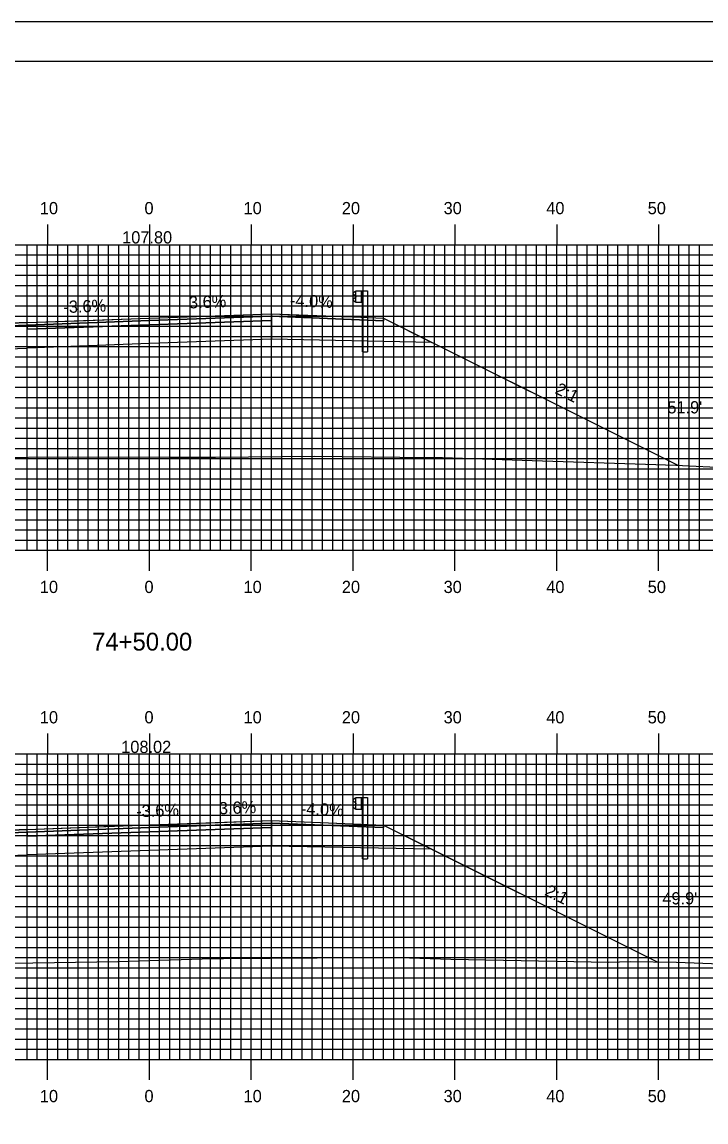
# Model space of a CAD drawing. Extents: x 1761004 to 1761347, y 442591 to 442811.
# Drawn here: x 1761157.2 to 1761224.4, y 442702.5 to 442810.5 of the extents above; entities that cross this region are included whole.
import ezdxf

# ---------------------------------------------------------------- set-up
doc = ezdxf.new("R2010")
doc.units = 0
for name, color, linetype in [('ANNOTATION', 7, 'Continuous'), ('BORDER', 7, 'Continuous'), ('D_Guardrail_Beam_Rt', 7, 'Continuous'), ('D_Roadway_Centerline', 7, 'Continuous'), ('D_Roadway_Centerline_Text', 7, 'Continuous'), ('D_Roadway_Edge_Shoulder', 7, 'Continuous'), ('D_Roadway_Edge_TW', 7, 'Continuous'), ('D_Roadway_Pavement', 7, 'Continuous'), ('D_Roadway_SlopeLines', 7, 'Continuous'), ('D_Roadway_SubGrade', 7, 'Continuous'), ('D_Text_Standard', 7, 'Continuous'), ('H_V ANNOTATION', 7, 'Continuous'), ('MAJOR', 7, 'Continuous'), ('MINOR', 7, 'Continuous'), ('PLOT BOUNDARY', 7, 'Continuous'), ('S_Roadway_Centerline', 7, 'Continuous')]:
    doc.layers.add(name, color=color, linetype=linetype)

msp = doc.modelspace()

# ---------------------------------------------------------------- linework, layer by layer
at = {"layer": 'BORDER'}
msp.add_lwpolyline([(1761020.13, 442596.67), (1761340.13, 442596.67), (1761340.13, 442806.67), (1761020.13, 442806.67)], close=True, dxfattribs=at)
at = {"layer": 'D_Guardrail_Beam_Rt'}
for p, q in [((1761189.91, 442784.06), (1761189.76, 442783.96)), ((1761189.76, 442783.81), (1761189.96, 442783.68)), ((1761190, 442784.08), (1761189.92, 442784.06)), ((1761189.99, 442783.61), (1761189.99, 442783.54)), ((1761190, 442784.16), (1761190.69, 442784.16)), ((1761190, 442782.99), (1761190, 442784.16)), ((1761190.52, 442784.16), (1761190.52, 442782.99)), ((1761190.62, 442784.16), (1761190.62, 442782.99)), ((1761190.69, 442784.16), (1761191.16, 442784.16)), ((1761190.69, 442784.16), (1761190.69, 442782.99)), ((1761191.16, 442784.16), (1761191.16, 442778.16)), ((1761189.96, 442783.48), (1761189.76, 442783.34)), ((1761189.76, 442783.2), (1761189.91, 442783.1)), ((1761189.92, 442783.09), (1761190, 442783.08)), ((1761190.69, 442782.99), (1761190, 442782.99)), ((1761190.66, 442778.16), (1761190.66, 442782.99)), ((1761190.66, 442778.16), (1761191.16, 442778.16)), ((1761189.91, 442734.28), (1761189.76, 442734.18)), ((1761189.76, 442734.03), (1761189.96, 442733.9)), ((1761190, 442734.3), (1761189.92, 442734.28)), ((1761190, 442734.38), (1761190.69, 442734.38)), ((1761190, 442733.21), (1761190, 442734.38)), ((1761190.52, 442734.38), (1761190.52, 442733.21)), ((1761190.62, 442734.38), (1761190.62, 442733.21)), ((1761190.69, 442734.38), (1761191.16, 442734.38)), ((1761190.69, 442734.38), (1761190.69, 442733.21)), ((1761191.16, 442734.38), (1761191.16, 442728.38)), ((1761189.96, 442733.7), (1761189.76, 442733.56)), ((1761189.76, 442733.42), (1761189.91, 442733.32)), ((1761189.92, 442733.31), (1761190, 442733.3)), ((1761189.99, 442733.83), (1761189.99, 442733.76)), ((1761190.69, 442733.21), (1761190, 442733.21)), ((1761190.66, 442728.38), (1761190.66, 442733.21)), ((1761190.66, 442728.38), (1761191.16, 442728.38))]:
    msp.add_line(p, q, dxfattribs=at)
for centre, major_axis, start_param, end_param in [((1761189.81, 442783.88), (-0.0877, 0), 5.323254, 7.243116), ((1761189.93, 442784.02), (-0.0417, 0), 4.907132, 5.323254), ((1761189.91, 442783.61), (0.0789, 0), 0, 0.959931), ((1761189.81, 442783.27), (-0.0877, 0), 5.323254, 7.243116), ((1761189.93, 442783.13), (-0.0417, 0), 0.959931, 1.376053), ((1761189.91, 442783.54), (0.0789, 0), 5.323254, 6.283185), ((1761189.81, 442734.1), (-0.0877, 0), 5.323254, 7.243116), ((1761189.93, 442734.24), (-0.0417, 0), 4.907132, 5.323254), ((1761189.81, 442733.49), (-0.0877, 0), 5.323254, 7.243116), ((1761189.93, 442733.35), (-0.0417, 0), 0.959931, 1.376053), ((1761189.91, 442733.83), (0.0789, 0), 0, 0.959931), ((1761189.91, 442733.76), (0.0789, 0), 5.323254, 6.283185)]:
    msp.add_ellipse(centre, major_axis=major_axis, ratio=0.995501, start_param=start_param, end_param=end_param, dxfattribs=at)
at = {"layer": 'D_Roadway_Centerline'}
for points in [[(1761153.4, 442780.86), (1761157.73, 442781.03), (1761162.64, 442781.21), (1761169.72, 442781.46), (1761169.73, 442781.47), (1761169.73, 442781.47), (1761172.49, 442781.56), (1761181.73, 442781.9), (1761187.35, 442781.67), (1761189.73, 442781.58), (1761189.73, 442781.58), (1761192.73, 442781.46), (1761192.73, 442781.45), (1761194.56, 442780.54), (1761197.48, 442779.08), (1761197.49, 442779.08), (1761212.78, 442771.43), (1761221.61, 442767.02), (1761221.63, 442767.01)], [(1761120.16, 442717.53), (1761133.13, 442724.02), (1761141.43, 442728.17), (1761146.73, 442730.81), (1761146.74, 442730.81), (1761149.72, 442730.93), (1761149.73, 442730.93), (1761157.72, 442731.25), (1761157.73, 442731.25), (1761166.12, 442731.56), (1761169.73, 442731.69), (1761175.62, 442731.9), (1761181.72, 442732.12), (1761181.73, 442732.12), (1761181.73, 442732.12), (1761185.69, 442731.96), (1761189.73, 442731.8), (1761192.73, 442731.68), (1761196.28, 442729.9), (1761197.48, 442729.3), (1761197.48, 442729.3), (1761202.44, 442726.82), (1761219.6, 442718.24)]]:
    msp.add_lwpolyline(points, dxfattribs=at)
at = {"layer": 'D_Roadway_Edge_Shoulder'}
for points in [[(1761181.73, 442781.9), (1761189.73, 442781.58), (1761189.73, 442781.58), (1761192.73, 442781.46), (1761192.73, 442781.21), (1761181.73, 442781.65)], [(1761157.73, 442781.03), (1761149.73, 442780.71), (1761149.73, 442780.71), (1761146.73, 442780.59), (1761146.73, 442780.34), (1761157.73, 442780.78)], [(1761181.73, 442732.12), (1761189.73, 442731.8), (1761189.73, 442731.8), (1761192.73, 442731.68), (1761192.73, 442731.43), (1761181.73, 442731.87)], [(1761157.73, 442731.25), (1761149.73, 442730.93), (1761149.73, 442730.93), (1761146.73, 442730.81), (1761146.73, 442730.56), (1761157.73, 442731)]]:
    msp.add_lwpolyline(points, close=True, dxfattribs=at)
at = {"layer": 'D_Roadway_Edge_TW'}
for points in [[(1761157.73, 442780.78), (1761157.73, 442781.03), (1761169.73, 442781.47), (1761181.73, 442781.9), (1761181.73, 442781.65), (1761169.73, 442781.22)], [(1761157.73, 442731), (1761157.73, 442731.25), (1761169.73, 442731.69), (1761181.73, 442732.12), (1761181.73, 442731.87), (1761169.73, 442731.44)]]:
    msp.add_lwpolyline(points, close=True, dxfattribs=at)
at = {"layer": 'D_Roadway_Pavement'}
for points in [[(1761157.73, 442780.37), (1761157.73, 442780.78), (1761169.73, 442781.22), (1761181.73, 442781.65), (1761181.73, 442781.23), (1761169.73, 442780.8)], [(1761157.73, 442730.59), (1761157.73, 442731), (1761169.73, 442731.44), (1761181.73, 442731.87), (1761181.73, 442731.45), (1761169.73, 442731.02)]]:
    msp.add_lwpolyline(points, close=True, dxfattribs=at)
for points in [[(1761181.73, 442781.65), (1761181.73, 442781.23)], [(1761157.73, 442780.78), (1761157.73, 442780.37)], [(1761181.73, 442731.87), (1761181.73, 442731.45)], [(1761157.73, 442731), (1761157.73, 442730.59)]]:
    msp.add_lwpolyline(points, dxfattribs=at)
at = {"layer": 'D_Roadway_SlopeLines'}
for points in [[(1761192.73, 442781.46), (1761221.63, 442767.01)], [(1761192.73, 442731.68), (1761219.6, 442718.24)]]:
    msp.add_lwpolyline(points, dxfattribs=at)
at = {"layer": 'D_Roadway_SubGrade'}
for points in [[(1761157.73, 442778.53), (1761157.73, 442780.78), (1761157.73, 442780.37), (1761169.73, 442780.8), (1761181.73, 442781.23), (1761181.73, 442781.65), (1761181.73, 442779.4), (1761169.73, 442778.97)], [(1761181.73, 442781.23), (1761181.73, 442781.65), (1761192.73, 442781.21), (1761192.73, 442781.46), (1761197.48, 442779.08), (1761181.73, 442779.4)], [(1761157.73, 442780.37), (1761157.73, 442780.78), (1761146.73, 442780.34), (1761146.73, 442780.59), (1761141.43, 442777.95), (1761157.73, 442778.53)], [(1761157.73, 442728.75), (1761157.73, 442731), (1761157.73, 442730.59), (1761169.73, 442731.02), (1761181.73, 442731.45), (1761181.73, 442731.87), (1761181.73, 442729.62), (1761169.73, 442729.19)], [(1761181.73, 442731.45), (1761181.73, 442731.87), (1761192.73, 442731.43), (1761192.73, 442731.68), (1761197.48, 442729.3), (1761181.73, 442729.62)], [(1761157.73, 442730.59), (1761157.73, 442731), (1761146.73, 442730.56), (1761146.73, 442730.81), (1761141.43, 442728.17), (1761157.73, 442728.75)]]:
    msp.add_lwpolyline(points, close=True, dxfattribs=at)
at = {"layer": 'MAJOR'}
for p, q in [((1761159.73, 442790.67), (1761159.73, 442788.67)), ((1761169.73, 442790.67), (1761169.73, 442788.67)), ((1761179.73, 442790.67), (1761179.73, 442788.67)), ((1761189.73, 442790.67), (1761189.73, 442788.67)), ((1761199.73, 442790.67), (1761199.73, 442788.67)), ((1761209.73, 442790.67), (1761209.73, 442788.67)), ((1761219.73, 442790.67), (1761219.73, 442788.67)), ((1761029.73, 442788.67), (1761309.73, 442788.67)), ((1761029.73, 442788.67), (1761309.73, 442788.67)), ((1761159.73, 442758.67), (1761159.73, 442788.67)), ((1761169.73, 442758.67), (1761169.73, 442788.67)), ((1761179.73, 442758.67), (1761179.73, 442788.67)), ((1761189.73, 442758.67), (1761189.73, 442788.67)), ((1761199.73, 442758.67), (1761199.73, 442788.67)), ((1761209.73, 442758.67), (1761209.73, 442788.67)), ((1761219.73, 442758.67), (1761219.73, 442788.67)), ((1761029.73, 442783.67), (1761309.73, 442783.67)), ((1761029.73, 442778.67), (1761309.73, 442778.67)), ((1761029.73, 442773.67), (1761309.73, 442773.67)), ((1761029.73, 442768.67), (1761309.73, 442768.67)), ((1761029.73, 442763.67), (1761309.73, 442763.67)), ((1761029.73, 442758.67), (1761309.73, 442758.67)), ((1761029.73, 442758.67), (1761309.73, 442758.67)), ((1761159.73, 442756.66), (1761159.73, 442758.67)), ((1761169.73, 442756.66), (1761169.73, 442758.67)), ((1761179.73, 442756.66), (1761179.73, 442758.67)), ((1761189.73, 442756.66), (1761189.73, 442758.67)), ((1761199.73, 442756.66), (1761199.73, 442758.67)), ((1761209.73, 442756.66), (1761209.73, 442758.67)), ((1761219.73, 442756.66), (1761219.73, 442758.67)), ((1761159.73, 442740.67), (1761159.73, 442738.67)), ((1761169.73, 442740.67), (1761169.73, 442738.67)), ((1761179.73, 442740.67), (1761179.73, 442738.67)), ((1761189.73, 442740.67), (1761189.73, 442738.67)), ((1761199.73, 442740.67), (1761199.73, 442738.67)), ((1761209.73, 442740.67), (1761209.73, 442738.67)), ((1761219.73, 442740.67), (1761219.73, 442738.67)), ((1761029.73, 442738.67), (1761309.73, 442738.67)), ((1761029.73, 442738.67), (1761309.73, 442738.67)), ((1761159.73, 442708.67), (1761159.73, 442738.67)), ((1761169.73, 442708.67), (1761169.73, 442738.67)), ((1761179.73, 442708.67), (1761179.73, 442738.67)), ((1761189.73, 442708.67), (1761189.73, 442738.67)), ((1761199.73, 442708.67), (1761199.73, 442738.67)), ((1761209.73, 442708.67), (1761209.73, 442738.67)), ((1761219.73, 442708.67), (1761219.73, 442738.67)), ((1761029.73, 442733.67), (1761309.73, 442733.67)), ((1761029.73, 442728.67), (1761309.73, 442728.67)), ((1761029.73, 442723.67), (1761309.73, 442723.67)), ((1761029.73, 442718.67), (1761309.73, 442718.67)), ((1761029.73, 442713.67), (1761309.73, 442713.67)), ((1761029.73, 442708.67), (1761309.73, 442708.67)), ((1761029.73, 442708.67), (1761309.73, 442708.67)), ((1761159.73, 442706.66), (1761159.73, 442708.67)), ((1761169.73, 442706.66), (1761169.73, 442708.67)), ((1761179.73, 442706.66), (1761179.73, 442708.67)), ((1761189.73, 442706.66), (1761189.73, 442708.67)), ((1761199.73, 442706.66), (1761199.73, 442708.67)), ((1761209.73, 442706.66), (1761209.73, 442708.67)), ((1761219.73, 442706.66), (1761219.73, 442708.67))]:
    msp.add_line(p, q, dxfattribs=at)
at = {"layer": 'MINOR'}
for p, q in [((1761157.73, 442758.67), (1761157.73, 442788.67)), ((1761158.73, 442758.67), (1761158.73, 442788.67)), ((1761160.73, 442758.67), (1761160.73, 442788.67)), ((1761161.73, 442758.67), (1761161.73, 442788.67)), ((1761162.73, 442758.67), (1761162.73, 442788.67)), ((1761163.73, 442758.67), (1761163.73, 442788.67)), ((1761164.73, 442758.67), (1761164.73, 442788.67)), ((1761165.73, 442758.67), (1761165.73, 442788.67)), ((1761166.73, 442758.67), (1761166.73, 442788.67)), ((1761167.73, 442758.67), (1761167.73, 442788.67)), ((1761168.73, 442758.67), (1761168.73, 442788.67)), ((1761170.73, 442758.67), (1761170.73, 442788.67)), ((1761171.73, 442758.67), (1761171.73, 442788.67)), ((1761172.73, 442758.67), (1761172.73, 442788.67)), ((1761173.73, 442758.67), (1761173.73, 442788.67)), ((1761174.73, 442758.67), (1761174.73, 442788.67)), ((1761175.73, 442758.67), (1761175.73, 442788.67)), ((1761176.73, 442758.67), (1761176.73, 442788.67)), ((1761177.73, 442758.67), (1761177.73, 442788.67)), ((1761178.73, 442758.67), (1761178.73, 442788.67)), ((1761180.73, 442758.67), (1761180.73, 442788.67)), ((1761181.73, 442758.67), (1761181.73, 442788.67)), ((1761182.73, 442758.67), (1761182.73, 442788.67)), ((1761183.73, 442758.67), (1761183.73, 442788.67)), ((1761184.73, 442758.67), (1761184.73, 442788.67)), ((1761185.73, 442758.67), (1761185.73, 442788.67)), ((1761186.73, 442758.67), (1761186.73, 442788.67)), ((1761187.73, 442758.67), (1761187.73, 442788.67)), ((1761188.73, 442758.67), (1761188.73, 442788.67)), ((1761190.73, 442758.67), (1761190.73, 442788.67)), ((1761191.73, 442758.67), (1761191.73, 442788.67)), ((1761192.73, 442758.67), (1761192.73, 442788.67)), ((1761193.73, 442758.67), (1761193.73, 442788.67)), ((1761194.73, 442758.67), (1761194.73, 442788.67)), ((1761195.73, 442758.67), (1761195.73, 442788.67)), ((1761196.73, 442758.67), (1761196.73, 442788.67)), ((1761197.73, 442758.67), (1761197.73, 442788.67)), ((1761198.73, 442758.67), (1761198.73, 442788.67)), ((1761200.73, 442758.67), (1761200.73, 442788.67)), ((1761201.73, 442758.67), (1761201.73, 442788.67)), ((1761202.73, 442758.67), (1761202.73, 442788.67)), ((1761203.73, 442758.67), (1761203.73, 442788.67)), ((1761204.73, 442758.67), (1761204.73, 442788.67)), ((1761205.73, 442758.67), (1761205.73, 442788.67)), ((1761206.73, 442758.67), (1761206.73, 442788.67)), ((1761207.73, 442758.67), (1761207.73, 442788.67)), ((1761208.73, 442758.67), (1761208.73, 442788.67)), ((1761210.73, 442758.67), (1761210.73, 442788.67)), ((1761211.73, 442758.67), (1761211.73, 442788.67)), ((1761212.73, 442758.67), (1761212.73, 442788.67)), ((1761213.73, 442758.67), (1761213.73, 442788.67)), ((1761214.73, 442758.67), (1761214.73, 442788.67)), ((1761215.73, 442758.67), (1761215.73, 442788.67)), ((1761216.73, 442758.67), (1761216.73, 442788.67)), ((1761217.73, 442758.67), (1761217.73, 442788.67)), ((1761218.73, 442758.67), (1761218.73, 442788.67)), ((1761220.73, 442758.67), (1761220.73, 442788.67)), ((1761221.73, 442758.67), (1761221.73, 442788.67)), ((1761222.73, 442758.67), (1761222.73, 442788.67)), ((1761223.73, 442758.67), (1761223.73, 442788.67)), ((1761029.73, 442787.67), (1761309.73, 442787.67)), ((1761029.73, 442786.67), (1761309.73, 442786.67)), ((1761029.73, 442785.67), (1761309.73, 442785.67)), ((1761029.73, 442784.67), (1761309.73, 442784.67)), ((1761029.73, 442782.67), (1761309.73, 442782.67)), ((1761029.73, 442781.67), (1761309.73, 442781.67)), ((1761029.73, 442780.67), (1761309.73, 442780.67)), ((1761029.73, 442779.67), (1761309.73, 442779.67)), ((1761029.73, 442777.67), (1761309.73, 442777.67)), ((1761029.73, 442776.67), (1761309.73, 442776.67)), ((1761029.73, 442775.67), (1761309.73, 442775.67)), ((1761029.73, 442774.67), (1761309.73, 442774.67)), ((1761029.73, 442772.67), (1761309.73, 442772.67)), ((1761029.73, 442771.67), (1761309.73, 442771.67)), ((1761029.73, 442770.67), (1761309.73, 442770.67)), ((1761029.73, 442769.67), (1761309.73, 442769.67)), ((1761029.73, 442767.67), (1761309.73, 442767.67)), ((1761029.73, 442766.67), (1761309.73, 442766.67)), ((1761029.73, 442765.67), (1761309.73, 442765.67)), ((1761029.73, 442764.67), (1761309.73, 442764.67)), ((1761029.73, 442762.67), (1761309.73, 442762.67)), ((1761029.73, 442761.67), (1761309.73, 442761.67)), ((1761029.73, 442760.67), (1761309.73, 442760.67)), ((1761029.73, 442759.67), (1761309.73, 442759.67)), ((1761157.73, 442708.67), (1761157.73, 442738.67)), ((1761158.73, 442708.67), (1761158.73, 442738.67)), ((1761160.73, 442708.67), (1761160.73, 442738.67)), ((1761161.73, 442708.67), (1761161.73, 442738.67)), ((1761162.73, 442708.67), (1761162.73, 442738.67)), ((1761163.73, 442708.67), (1761163.73, 442738.67)), ((1761164.73, 442708.67), (1761164.73, 442738.67)), ((1761165.73, 442708.67), (1761165.73, 442738.67)), ((1761166.73, 442708.67), (1761166.73, 442738.67)), ((1761167.73, 442708.67), (1761167.73, 442738.67)), ((1761168.73, 442708.67), (1761168.73, 442738.67)), ((1761170.73, 442708.67), (1761170.73, 442738.67)), ((1761171.73, 442708.67), (1761171.73, 442738.67)), ((1761172.73, 442708.67), (1761172.73, 442738.67)), ((1761173.73, 442708.67), (1761173.73, 442738.67)), ((1761174.73, 442708.67), (1761174.73, 442738.67)), ((1761175.73, 442708.67), (1761175.73, 442738.67)), ((1761176.73, 442708.67), (1761176.73, 442738.67)), ((1761177.73, 442708.67), (1761177.73, 442738.67)), ((1761178.73, 442708.67), (1761178.73, 442738.67)), ((1761180.73, 442708.67), (1761180.73, 442738.67)), ((1761181.73, 442708.67), (1761181.73, 442738.67)), ((1761182.73, 442708.67), (1761182.73, 442738.67)), ((1761183.73, 442708.67), (1761183.73, 442738.67)), ((1761184.73, 442708.67), (1761184.73, 442738.67)), ((1761185.73, 442708.67), (1761185.73, 442738.67)), ((1761186.73, 442708.67), (1761186.73, 442738.67)), ((1761187.73, 442708.67), (1761187.73, 442738.67)), ((1761188.73, 442708.67), (1761188.73, 442738.67)), ((1761190.73, 442708.67), (1761190.73, 442738.67)), ((1761191.73, 442708.67), (1761191.73, 442738.67)), ((1761192.73, 442708.67), (1761192.73, 442738.67)), ((1761193.73, 442708.67), (1761193.73, 442738.67)), ((1761194.73, 442708.67), (1761194.73, 442738.67)), ((1761195.73, 442708.67), (1761195.73, 442738.67)), ((1761196.73, 442708.67), (1761196.73, 442738.67)), ((1761197.73, 442708.67), (1761197.73, 442738.67)), ((1761198.73, 442708.67), (1761198.73, 442738.67)), ((1761200.73, 442708.67), (1761200.73, 442738.67)), ((1761201.73, 442708.67), (1761201.73, 442738.67)), ((1761202.73, 442708.67), (1761202.73, 442738.67)), ((1761203.73, 442708.67), (1761203.73, 442738.67)), ((1761204.73, 442708.67), (1761204.73, 442738.67)), ((1761205.73, 442708.67), (1761205.73, 442738.67)), ((1761206.73, 442708.67), (1761206.73, 442738.67)), ((1761207.73, 442708.67), (1761207.73, 442738.67)), ((1761208.73, 442708.67), (1761208.73, 442738.67)), ((1761210.73, 442708.67), (1761210.73, 442738.67)), ((1761211.73, 442708.67), (1761211.73, 442738.67)), ((1761212.73, 442708.67), (1761212.73, 442738.67)), ((1761213.73, 442708.67), (1761213.73, 442738.67)), ((1761214.73, 442708.67), (1761214.73, 442738.67)), ((1761215.73, 442708.67), (1761215.73, 442738.67)), ((1761216.73, 442708.67), (1761216.73, 442738.67)), ((1761217.73, 442708.67), (1761217.73, 442738.67)), ((1761218.73, 442708.67), (1761218.73, 442738.67)), ((1761220.73, 442708.67), (1761220.73, 442738.67)), ((1761221.73, 442708.67), (1761221.73, 442738.67)), ((1761222.73, 442708.67), (1761222.73, 442738.67)), ((1761223.73, 442708.67), (1761223.73, 442738.67)), ((1761029.73, 442737.67), (1761309.73, 442737.67)), ((1761029.73, 442736.67), (1761309.73, 442736.67)), ((1761029.73, 442735.67), (1761309.73, 442735.67)), ((1761029.73, 442734.67), (1761309.73, 442734.67)), ((1761029.73, 442732.67), (1761309.73, 442732.67)), ((1761029.73, 442731.67), (1761309.73, 442731.67)), ((1761029.73, 442730.67), (1761309.73, 442730.67)), ((1761029.73, 442729.67), (1761309.73, 442729.67)), ((1761029.73, 442727.67), (1761309.73, 442727.67)), ((1761029.73, 442726.67), (1761309.73, 442726.67)), ((1761029.73, 442725.67), (1761309.73, 442725.67)), ((1761029.73, 442724.67), (1761309.73, 442724.67)), ((1761029.73, 442722.67), (1761309.73, 442722.67)), ((1761029.73, 442721.67), (1761309.73, 442721.67)), ((1761029.73, 442720.67), (1761309.73, 442720.67)), ((1761029.73, 442719.67), (1761309.73, 442719.67)), ((1761029.73, 442717.67), (1761309.73, 442717.67)), ((1761029.73, 442716.67), (1761309.73, 442716.67)), ((1761029.73, 442715.67), (1761309.73, 442715.67)), ((1761029.73, 442714.67), (1761309.73, 442714.67)), ((1761029.73, 442712.67), (1761309.73, 442712.67)), ((1761029.73, 442711.67), (1761309.73, 442711.67)), ((1761029.73, 442710.67), (1761309.73, 442710.67)), ((1761029.73, 442709.67), (1761309.73, 442709.67))]:
    msp.add_line(p, q, dxfattribs=at)
at = {"layer": 'PLOT BOUNDARY'}
msp.add_lwpolyline([(1761003.94, 442590.55), (1761343.94, 442590.55), (1761343.94, 442810.55), (1761003.94, 442810.55)], close=True, dxfattribs=at)
at = {"layer": 'S_Roadway_Centerline'}
for points in [[(1761109.02, 442767.52), (1761115.76, 442767.67), (1761123.28, 442767.68), (1761131.38, 442767.72), (1761140.83, 442767.63), (1761147.32, 442767.75), (1761153.45, 442767.79), (1761162.23, 442767.86), (1761171.78, 442767.82), (1761176.21, 442767.8), (1761185.96, 442767.92), (1761197.12, 442767.78), (1761197.8, 442767.78), (1761198.51, 442767.77), (1761207.32, 442767.48), (1761219.46, 442767.1), (1761220.4, 442767.06), (1761221.43, 442767.02), (1761232.1, 442766.5)], [(1761109.37, 442717.44), (1761118.81, 442717.54), (1761130.94, 442717.43), (1761142.25, 442717.71), (1761148.13, 442718.11), (1761154.04, 442718.1), (1761160.42, 442718.19), (1761166.65, 442718.27), (1761174.9, 442718.53), (1761177, 442718.57), (1761190.8, 442718.67), (1761195.27, 442718.63), (1761199.34, 442718.52), (1761214.85, 442718.21), (1761216.92, 442718.28), (1761221.47, 442718.21), (1761237.8, 442717.59)]]:
    msp.add_lwpolyline(points, dxfattribs=at)

# ---------------------------------------------------------------- texts
at = {"layer": 'ANNOTATION'}
for s, rotation, p in [('3.6%', 2.0618, (1761173.64, 442782.41)), ('-4.0%', 357.7094, (1761183.52, 442782.63)), ('-3.6%', 2.0616, (1761161.31, 442781.96)), ('2:1', 333.435, (1761209.48, 442774.12)), ('3.6%', 2.0617, (1761176.58, 442732.73)), ('-3.6%', 2.0618, (1761168.46, 442732.44)), ('-4.0%', 357.7093, (1761184.59, 442732.71)), ('2:1', 333.4349, (1761208.47, 442724.84))]:
    msp.add_text(s, height=1.2, rotation=rotation, dxfattribs=at).set_placement(p)
at = {"layer": 'D_Roadway_Centerline'}
for s, p in [('C', (1761169.72, 442781.47)), ('L', (1761169.73, 442781.46)), ('C', (1761169.72, 442731.69)), ('L', (1761169.73, 442731.68))]:
    msp.add_text(s, height=0.0146, dxfattribs=at).set_placement(p)
at = {"layer": 'D_Roadway_Centerline_Text'}
for s, p in [('107.80', (1761167.06, 442788.8)), ('108.02', (1761166.97, 442738.76))]:
    msp.add_text(s, height=1.2, dxfattribs=at).set_placement(p)
at = {"layer": 'D_Text_Standard'}
for s, p in [("51.9'", (1761220.59, 442772.11)), ("49.9'", (1761220.1, 442723.89))]:
    msp.add_text(s, height=1.2, dxfattribs=at).set_placement(p)
at = {"layer": 'H_V ANNOTATION'}
for s, height, p in [('10', 1.2, (1761158.98, 442791.67)), ('0', 1.2, (1761169.25, 442791.67)), ('10', 1.2, (1761178.98, 442791.67)), ('20', 1.2, (1761188.63, 442791.67)), ('30', 1.2, (1761198.62, 442791.67)), ('40', 1.2, (1761208.7, 442791.67)), ('50', 1.2, (1761218.66, 442791.67)), ('10', 1.2, (1761158.98, 442754.47)), ('0', 1.2, (1761169.25, 442754.47)), ('10', 1.2, (1761178.98, 442754.47)), ('20', 1.2, (1761188.63, 442754.47)), ('30', 1.2, (1761198.62, 442754.47)), ('40', 1.2, (1761208.7, 442754.47)), ('50', 1.2, (1761218.66, 442754.47)), ('74+50.00', 1.75, (1761164.11, 442748.82)), ('10', 1.2, (1761158.98, 442741.67)), ('0', 1.2, (1761169.25, 442741.67)), ('10', 1.2, (1761178.98, 442741.67)), ('20', 1.2, (1761188.63, 442741.67)), ('30', 1.2, (1761198.62, 442741.67)), ('40', 1.2, (1761208.7, 442741.67)), ('50', 1.2, (1761218.66, 442741.67)), ('10', 1.2, (1761158.98, 442704.47)), ('0', 1.2, (1761169.25, 442704.47)), ('10', 1.2, (1761178.98, 442704.47)), ('20', 1.2, (1761188.63, 442704.47)), ('30', 1.2, (1761198.62, 442704.47)), ('40', 1.2, (1761208.7, 442704.47)), ('50', 1.2, (1761218.66, 442704.47))]:
    msp.add_text(s, height=height, dxfattribs=at).set_placement(p)

doc.saveas('drawing.dxf')
